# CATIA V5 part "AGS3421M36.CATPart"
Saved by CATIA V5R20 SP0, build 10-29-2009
Part number: AGS3421M36
Definition: NONE
Nomenclature: AGS3421M36
Source: Unknown
Description: AGS3421M36
Bounding box of the stored display mesh (mm): x -30 to 50, y -21.312 to 21.312, z -19.25 to 19.25
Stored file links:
  C:\Users\Utente\Desktop\IO LAVORO\3D X SITO CF\X SITO\PLASTICA\AGS\AGS3421M36.CATPart
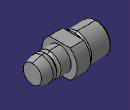
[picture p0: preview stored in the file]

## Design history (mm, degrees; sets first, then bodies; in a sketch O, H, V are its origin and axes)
Body1 "AGS3421M36" (main body)
  Solid1: solid without history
